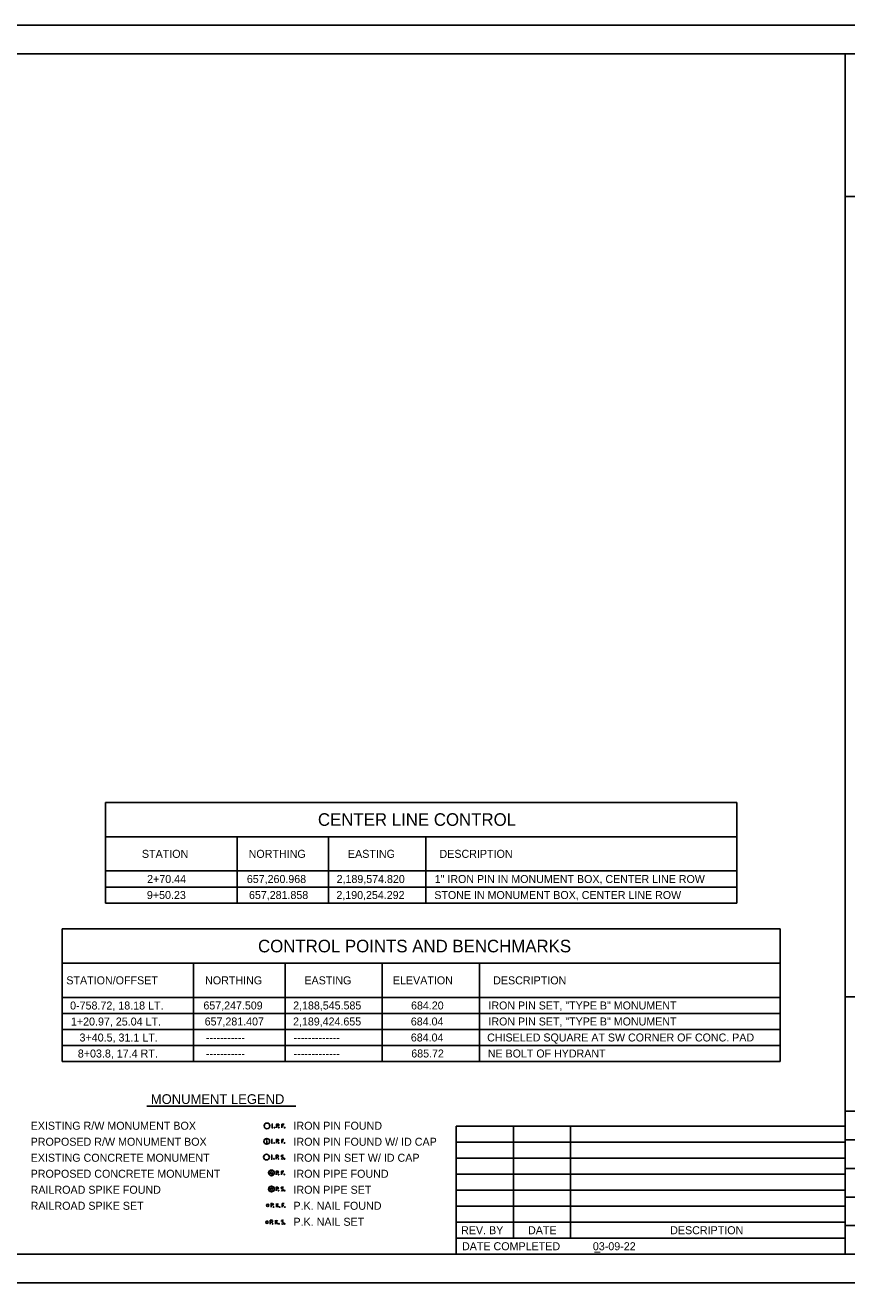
# Model space of a CAD drawing. Extents: x 54.5 to 95.1, y 4.7 to 26.7.
# Drawn here: x 72.18 to 86.55, y 4.72 to 26.72 of the extents above; entities that cross this region are included whole.
import ezdxf

# ---------------------------------------------------------------- set-up
doc = ezdxf.new("R2010")
doc.units = 0
for name, color, linetype in [('Default', 7, 'Continuous'), ('SH_Data', 7, 'Continuous'), ('SH_Text', 7, 'Continuous'), ('TX_P_10', 7, 'Continuous')]:
    doc.layers.add(name, color=color, linetype=linetype)

msp = doc.modelspace()

# ---------------------------------------------------------------- linework, layer by layer
at = {"layer": 'SH_Data'}
for p, q in [((73.585, 11.361), (73.585, 13.121)), ((73.585, 12.521), (84.626, 12.521)), ((73.585, 11.921), (84.626, 11.921)), ((73.585, 11.641), (84.626, 11.641)), ((72.824, 8.588), (72.824, 10.908)), ((72.824, 10.308), (85.387, 10.308)), ((72.824, 9.708), (85.387, 9.708)), ((72.824, 9.428), (85.387, 9.428))]:
    msp.add_line(p, q, dxfattribs=at)
at = {"layer": 'SH_Text'}
for p, q in [((86.523, 5.217), (86.523, 26.217)), ((86.523, 23.717), (88.023, 23.717)), ((86.523, 9.717), (88.023, 9.717)), ((74.308, 7.808), (76.911, 7.808)), ((86.523, 7.717), (88.023, 7.717)), ((76.492, 7.495), (76.509, 7.495)), ((76.492, 7.495), (76.509, 7.495)), ((76.5, 7.428), (76.5, 7.495)), ((76.671, 7.428), (76.671, 7.495)), ((76.671, 7.495), (76.709, 7.495)), ((76.492, 7.428), (76.509, 7.428)), ((76.577, 7.463), (76.604, 7.463)), ((76.671, 7.462), (76.698, 7.462)), ((79.72, 7.457), (79.72, 5.217)), ((79.72, 7.457), (86.523, 7.457)), ((80.72, 7.457), (80.72, 5.497)), ((81.72, 7.457), (81.72, 5.497)), ((76.404, 7.197), (76.404, 7.16)), ((76.488, 7.225), (76.504, 7.225)), ((76.488, 7.225), (76.504, 7.225)), ((76.488, 7.159), (76.504, 7.159)), ((76.496, 7.159), (76.496, 7.225)), ((76.573, 7.193), (76.599, 7.193)), ((76.666, 7.159), (76.666, 7.225)), ((76.666, 7.225), (76.705, 7.225)), ((76.666, 7.193), (76.694, 7.193)), ((79.72, 7.177), (86.523, 7.177)), ((86.523, 7.217), (88.023, 7.217)), ((76.483, 6.949), (76.5, 6.949)), ((76.483, 6.949), (76.5, 6.949)), ((76.483, 6.882), (76.5, 6.882)), ((76.492, 6.882), (76.492, 6.949)), ((76.568, 6.917), (76.595, 6.917)), ((76.663, 6.925), (76.693, 6.909)), ((79.72, 6.897), (86.523, 6.897)), ((76.57, 6.641), (76.596, 6.641)), ((76.663, 6.607), (76.663, 6.673)), ((76.663, 6.673), (76.702, 6.673)), ((76.663, 6.641), (76.691, 6.641)), ((79.72, 6.617), (86.523, 6.617)), ((86.523, 6.717), (88.023, 6.717)), ((76.57, 6.36), (76.596, 6.36)), ((76.664, 6.368), (76.695, 6.352)), ((79.72, 6.337), (86.523, 6.337)), ((86.523, 6.217), (88.023, 6.217)), ((76.481, 6.073), (76.508, 6.073)), ((76.575, 6.038), (76.575, 6.105)), ((76.575, 6.062), (76.607, 6.105)), ((76.585, 6.076), (76.613, 6.038)), ((76.673, 6.038), (76.673, 6.105)), ((76.673, 6.105), (76.712, 6.105)), ((76.673, 6.072), (76.701, 6.072)), ((79.72, 6.057), (86.523, 6.057)), ((76.467, 5.78), (76.494, 5.78)), ((76.56, 5.745), (76.56, 5.812)), ((76.56, 5.769), (76.592, 5.812)), ((76.57, 5.783), (76.598, 5.745)), ((76.666, 5.788), (76.696, 5.772)), ((79.72, 5.777), (86.523, 5.777)), ((86.523, 5.717), (88.023, 5.717)), ((79.72, 5.497), (86.523, 5.497)), ((86.523, 5.217), (86.523, 5.217))]:
    msp.add_line(p, q, dxfattribs=at)
for points in [[(54.523, 4.717), (88.523, 4.717), (88.523, 26.717), (54.523, 26.717)], [(56.023, 26.217), (88.023, 26.217), (88.023, 5.217), (56.023, 5.217)]]:
    msp.add_lwpolyline(points, close=True, dxfattribs=at)
for points in [[(76.604, 7.495), (76.577, 7.495), (76.577, 7.428)], [(76.599, 7.225), (76.573, 7.225), (76.573, 7.159)], [(76.595, 6.949), (76.568, 6.949), (76.568, 6.882)], [(76.596, 6.673), (76.57, 6.673), (76.57, 6.607)], [(76.596, 6.392), (76.57, 6.392), (76.57, 6.325)], [(76.508, 6.105), (76.481, 6.105), (76.481, 6.038)], [(76.494, 5.812), (76.467, 5.812), (76.467, 5.745)]]:
    msp.add_lwpolyline(points, dxfattribs=at)
for centre, radius in [((76.409, 7.461), 0.05), ((76.54, 7.432), 0.00583), ((76.617, 7.432), 0.00583), ((76.719, 7.432), 0.00583), ((76.404, 7.192), 0.05), ((76.404, 7.219), 0.00667), ((76.536, 7.163), 0.00583), ((76.613, 7.163), 0.00583), ((76.715, 7.163), 0.00583), ((76.4, 6.916), 0.05), ((76.532, 6.887), 0.00583), ((76.609, 6.887), 0.00583), ((76.715, 6.886), 0.00583), ((76.486, 6.64), 0.05), ((76.486, 6.64), 0.0206), ((76.61, 6.611), 0.00583), ((76.711, 6.611), 0.00583), ((76.486, 6.358), 0.05), ((76.486, 6.358), 0.0208), ((76.61, 6.33), 0.00583), ((76.717, 6.329), 0.00583), ((76.422, 6.071), 0.0207), ((76.522, 6.042), 0.00583), ((76.631, 6.042), 0.00583), ((76.722, 6.042), 0.00583), ((76.409, 5.778), 0.0206), ((76.507, 5.749), 0.00583), ((76.618, 5.749), 0.00583), ((76.718, 5.749), 0.00583)]:
    msp.add_circle(centre, radius, dxfattribs=at)
for centre, radius, start, end in [((76.601, 7.479), 0.0162, 278.8803, 81.1197), ((76.597, 7.209), 0.0162, 278.8803, 81.1197), ((76.593, 6.933), 0.0162, 278.8803, 81.1197), ((76.669, 6.935), 0.0118, 126.2587, 236.3676), ((76.678, 6.91), 0.0276, 223.6695, 304.3963), ((76.679, 6.914), 0.0349, 61.3463, 118.6537), ((76.683, 6.898), 0.0148, 311.4883, 47.9358), ((76.594, 6.657), 0.0162, 278.8803, 81.1197), ((76.594, 6.376), 0.0162, 278.8803, 81.1197), ((76.67, 6.378), 0.0118, 126.2587, 236.3676), ((76.68, 6.357), 0.0349, 61.3463, 118.6537), ((76.679, 6.353), 0.0276, 223.6695, 304.3963), ((76.685, 6.341), 0.0148, 311.4883, 47.9358), ((76.506, 6.089), 0.0162, 278.8803, 81.1197), ((76.491, 5.796), 0.0162, 278.8803, 81.1197), ((76.672, 5.798), 0.0118, 126.2587, 236.3676), ((76.681, 5.773), 0.0276, 223.6695, 304.3963), ((76.682, 5.777), 0.0349, 61.3463, 118.6537), ((76.686, 5.761), 0.0148, 311.4883, 47.9358)]:
    msp.add_arc(centre, radius, start, end, dxfattribs=at)
at = {"layer": 'TX_P_10'}
for p, q in [((73.585, 13.121), (84.626, 13.121)), ((84.626, 11.361), (84.626, 13.121)), ((75.885, 11.361), (75.885, 12.521)), ((77.485, 11.361), (77.485, 12.521)), ((79.185, 11.361), (79.185, 12.521)), ((73.585, 11.361), (84.626, 11.361)), ((72.824, 10.908), (85.387, 10.908)), ((85.387, 8.588), (85.387, 10.908)), ((75.124, 8.588), (75.124, 10.308)), ((76.724, 8.588), (76.724, 10.308)), ((78.424, 8.588), (78.424, 10.308)), ((80.124, 8.588), (80.124, 10.308)), ((72.824, 9.148), (85.387, 9.148)), ((72.824, 8.868), (85.387, 8.868)), ((72.824, 8.588), (85.387, 8.588))]:
    msp.add_line(p, q, dxfattribs=at)

# ---------------------------------------------------------------- texts
at = {"layer": 'Default'}
for s, height, p in [('2+70.44', 0.14, (74.312, 11.711)), ('657,260.968', 0.13934, (76.057, 11.711)), ('2,189,574.820', 0.13934, (77.627, 11.711)), ('1" IRON PIN IN MONUMENT BOX, CENTER LINE ROW', 0.13934, (79.343, 11.711)), ('9+50.23', 0.14, (74.308, 11.431)), ('657,281.858', 0.13934, (76.094, 11.431)), ('2,190,254.292', 0.13934, (77.623, 11.431)), ('STONE IN MONUMENT BOX, CENTER LINE ROW', 0.13934, (79.336, 11.431)), ('0-758.72, 18.18 LT.', 0.14, (72.965, 9.498)), ('657,247.509', 0.13934, (75.297, 9.499)), ('2,188,545.585', 0.13934, (76.867, 9.499)), ('684.20', 0.1393, (78.929, 9.499)), ('IRON PIN SET, "TYPE B" MONUMENT', 0.13934, (80.282, 9.499)), ('1+20.97, 25.04 LT.', 0.14, (72.979, 9.218)), ('657,281.407', 0.13934, (75.319, 9.219)), ('2,189,424.655', 0.13934, (76.865, 9.219)), ('684.04', 0.1393, (78.925, 9.219)), ('IRON PIN SET, "TYPE B" MONUMENT', 0.13934, (80.282, 9.219)), ('3+40.5, 31.1 LT.', 0.14, (73.13, 8.938)), ('684.04', 0.1393, (78.925, 8.939)), ('CHISELED SQUARE AT SW CORNER OF CONC. PAD', 0.13934, (80.26, 8.939)), ('8+03.8, 17.4 RT.', 0.14, (73.1, 8.658)), ('-----------', 0.13934, (75.341, 8.939)), ('-------------', 0.13934, (76.876, 8.939)), ('685.72', 0.1393, (78.933, 8.659)), ('NE BOLT OF HYDRANT', 0.13934, (80.271, 8.659)), ('-----------', 0.13934, (75.341, 8.659)), ('-------------', 0.13934, (76.876, 8.659))]:
    msp.add_text(s, height=height, dxfattribs=at).set_placement(p)
at = {"layer": 'SH_Data'}
for s, p in [('STATION', (74.221, 12.151)), ('NORTHING', (76.088, 12.151)), ('EASTING', (77.825, 12.151)), ('DESCRIPTION', (79.426, 12.151)), ('STATION/OFFSET', (72.899, 9.938)), ('NORTHING', (75.326, 9.938)), ('EASTING', (77.063, 9.938)), ('ELEVATION', (78.61, 9.938)), ('DESCRIPTION', (80.365, 9.938))]:
    msp.add_text(s, height=0.14, dxfattribs=at).set_placement(p)
at = {"layer": 'SH_Text'}
for s, height, p in [('CENTER LINE CONTROL', 0.22, (77.3, 12.711)), ('CONTROL POINTS AND BENCHMARKS', 0.22, (76.252, 10.498)), ('MONUMENT LEGEND', 0.17, (74.377, 7.846)), ('EXISTING R/W MONUMENT BOX', 0.14, (72.275, 7.395)), ('IRON PIN FOUND', 0.14, (76.872, 7.395)), ('PROPOSED R/W MONUMENT BOX', 0.14, (72.275, 7.115)), ('IRON PIN FOUND W/ ID CAP', 0.14, (76.872, 7.115)), ('EXISTING CONCRETE MONUMENT', 0.14, (72.275, 6.835)), ('IRON PIN SET W/ ID CAP', 0.14, (76.872, 6.835)), ('PROPOSED CONCRETE MONUMENT', 0.14, (72.275, 6.555)), ('IRON PIPE FOUND', 0.14, (76.872, 6.555)), ('RAILROAD SPIKE FOUND', 0.14, (72.275, 6.275)), ('IRON PIPE SET', 0.14, (76.872, 6.275)), ('RAILROAD SPIKE SET', 0.14, (72.275, 5.995)), ('P.K. NAIL FOUND', 0.14, (76.872, 5.995)), ('P.K. NAIL SET', 0.14, (76.872, 5.715)), ('REV. BY', 0.14, (79.804, 5.567)), ('DATE', 0.14, (80.975, 5.567)), ('DESCRIPTION', 0.14, (83.461, 5.567)), ('DATE COMPLETED           03-09-22', 0.14, (79.82, 5.287)), ('         _', 0.14, (81.667, 5.287))]:
    msp.add_text(s, height=height, dxfattribs=at).set_placement(p)

doc.saveas('drawing.dxf')
